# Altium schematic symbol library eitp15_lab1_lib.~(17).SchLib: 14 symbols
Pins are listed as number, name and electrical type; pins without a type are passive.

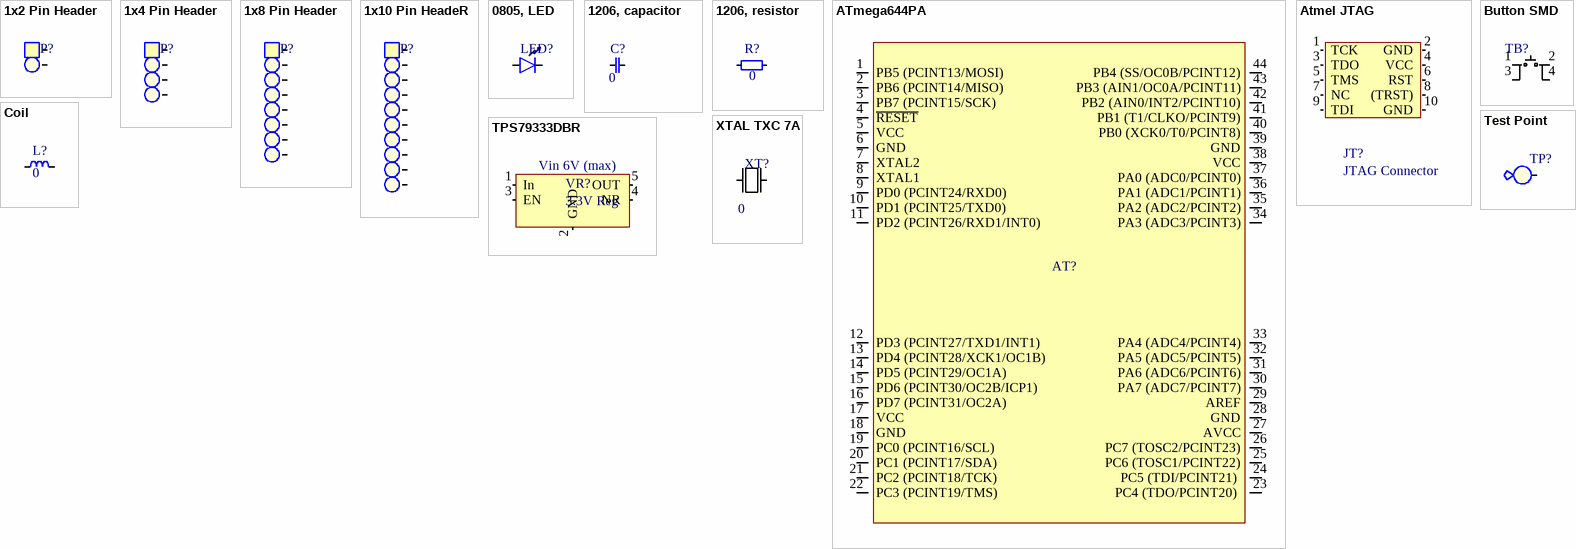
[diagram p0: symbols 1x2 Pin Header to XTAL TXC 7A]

## 1x2 Pin Header
designator P?  (value not drawn)
2.54 mm, TH; Value: 1x2 Pin Header
footprint 1x2HEADER (Pad Diameter 2 mm, Hole  1 mm, Pitch 2.54 mm)
pins: 1, 2

## 1x4 Pin Header
designator P?  (value not drawn)
2.54 mm, TH; Value: 1x2 Pin Header
footprint 1x4HEADER (Pad Diameter 2 mm, Hole  1 mm, Pitch 2.54 mm)
pins: 1, 2, 3, 4

## 1x8 Pin Header
designator P?  (value not drawn)
2.54 mm, TH; Value: 1x2 Pin Header
footprint 1x8HEADER (Pad Diameter 2 mm, Hole  1 mm, Pitch 2.54 mm)
pins: 1, 2, 3, 4, 5, 6, 7, 8

## 1x10 Pin HeadeR
designator P?  (value not drawn)
2.54 mm, TH; Value: 1x2 Pin Header
footprint 1x10HEADER (Pad Diameter 2 mm, Hole  1 mm, Pitch 2.54 mm)
pins: 1, 2, 3, 4, 5, 6, 7, 8, 9, 10

## 0805, LED
designator LED?  (value not drawn)
Value: 0805 LED
footprint 0805_led
pins: 0 Cathode, 1

## 1206, capacitor
designator C?  value 0  (hidden comment: *)
footprint 1206, capasitor (Generic 1206)
pins: 0, 1

## 1206, resistor
designator R?  value 0  (hidden comment: *)
Resistor
footprint 1206 (Generic 1206)
pins: 0, 1

## ATmega644PA
designator AT?
ATmega644PA - Small but big and PicoPower
footprint TQFP-44 (QFP, 44-Leads, Body 10,00x10,00mm, Pitch 0,80mm, IPC Medium Density)
pins: 1 PB5 (PCINT13/MOSI) , 2 PB6 (PCINT14/MISO) , 3 PB7 (PCINT15/SCK) , 4 ~{RESET}, 5 VCC, 6 GND, 7 XTAL2, 8 XTAL1, 9 PD0 (PCINT24/RXD0) , 10 PD1 (PCINT25/TXD0) , 11 PD2 (PCINT26/RXD1/INT0) , 12 PD3 (PCINT27/TXD1/INT1) , 13 PD4 (PCINT28/XCK1/OC1B) , 14 PD5 (PCINT29/OC1A) , 15 PD6 (PCINT30/OC2B/ICP1) , 16 PD7 (PCINT31/OC2A) , 17 VCC, 18 GND, 19 PC0 (PCINT16/SCL) , 20 PC1 (PCINT17/SDA) , 21 PC2 (PCINT18/TCK) , 22 PC3 (PCINT19/TMS) , 23 PC4 (TDO/PCINT20) , 24 PC5 (TDI/PCINT21) , 25 PC6 (TOSC1/PCINT22), 26 PC7 (TOSC2/PCINT23), 27 AVCC, 28 GND, 29 AREF, 30 PA7 (ADC7/PCINT7), 31 PA6 (ADC6/PCINT6), 32 PA5 (ADC5/PCINT5), 33 PA4 (ADC4/PCINT4), 34 PA3 (ADC3/PCINT3), 35 PA2 (ADC2/PCINT2), 36 PA1 (ADC1/PCINT1), 37 PA0 (ADC0/PCINT0), 38 VCC, 39 GND, 40 PB0 (XCK0/T0/PCINT8), 41 PB1 (T1/CLKO/PCINT9), 42 PB2 (AIN0/INT2/PCINT10), 43 PB3 (AIN1/OC0A/PCINT11), 44 PB4 (SS/OC0B/PCINT12)

## Atmel JTAG
designator JT?, comment JTAG Connector
Atmel JTAG Connector
footprint Atmel_JTAG
pins: 1 TCK, 2 GND, 3 TDO, 4 VCC, 5 TMS, 6 RST, 7 NC, 8 (TRST), 9 TDI, 10 GND

## Button SMD
designator TB?, comment Tactile Button  (value not drawn)
Tactile Switch Small Low; Value: Button SMD
footprint Button smd
pins: 1, 2, 3, 4

## Coil
designator L?  value 0  (hidden comment: *)
footprint 1812, coil
footprint 1210, Res
pins: 1, 2

## Test Point
designator TP?  (value not drawn)
Value: Test point
footprint testPoint (Diameter 2mm, Hole 0.3mm)
pins: 0

## TPS79333DBR
designator VR?, comment 3.3V Reg  Input Voltage: Vin 6V (max)
3.3V Reg, Ultra-Low Noise, 200 mA; Value: TPS79333DBVR; Drop Out: 102mV
footprint SOT23-5 (SOT23, 5-Leads, Body 2,90x2,80mm, Pitch 0,95mm, IPC Medium Density)
pins: 1 In, 2 GND, 3 EN, 4 NR, 5 OUT

## XTAL TXC 7A
designator XT?  value 0  (hidden comment: *)
16 MHz, SMD, 5mm x 3,2mm, 30 ppm
footprint XTAL_SMD_LP (Pad 1.7x2.4, Pitch 3.7)
pins: 1, 2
